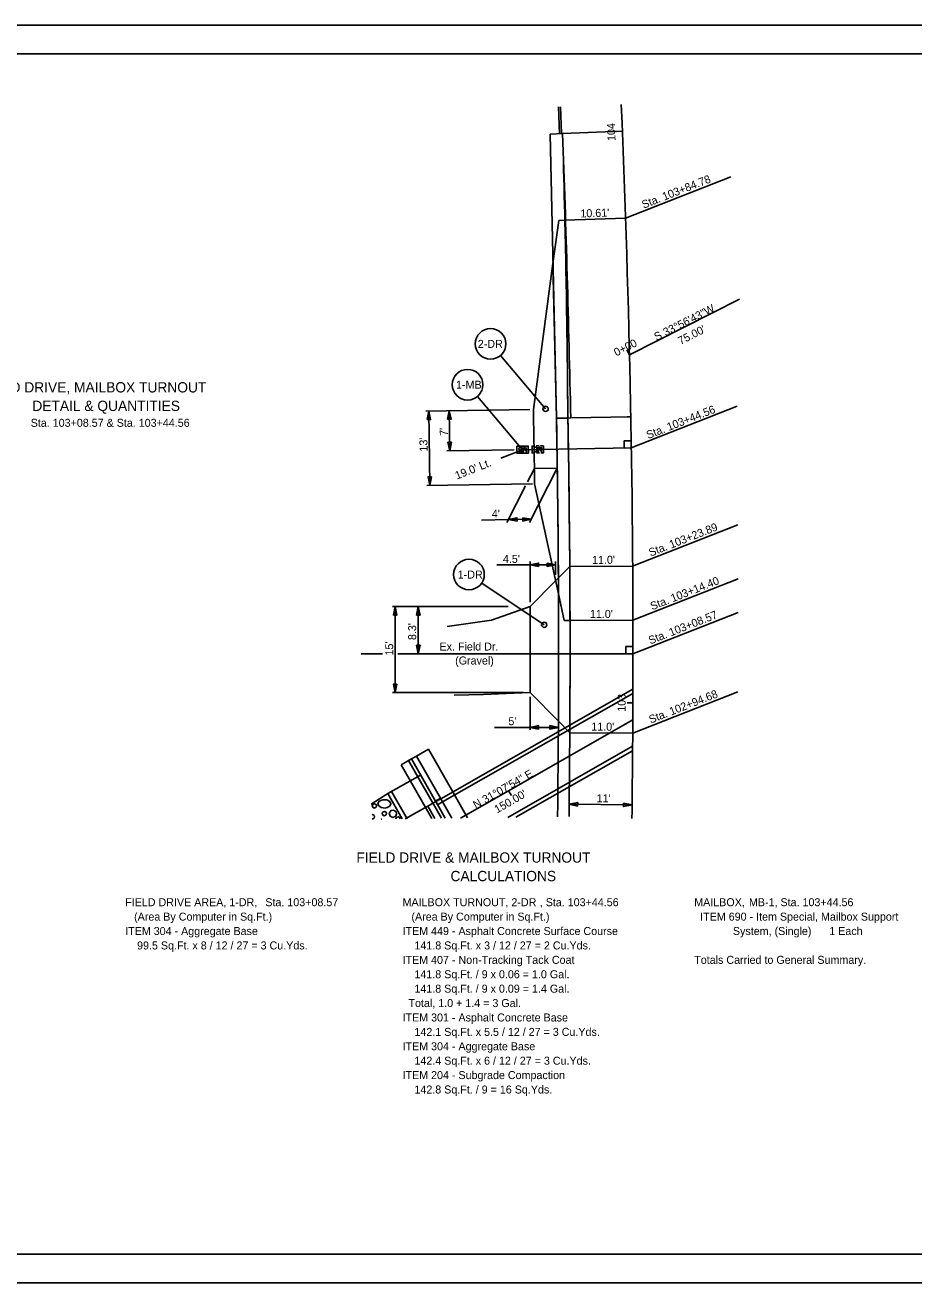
# Model space of a CAD drawing. Extents: x -736 to 9385, y -1086 to 4832.
# Drawn here: x 151.9 to 307.3, y -220 to 0 of the extents above; entities that cross this region are included whole.
import ezdxf

# ---------------------------------------------------------------- set-up
doc = ezdxf.new("R2010")
doc.units = 0
for name, color, linetype in [('_CIVIL_CONSTRUCTION', 7, 'Continuous'), ('DR_P_Culvert', 7, 'Continuous'), ('DR_X_Headwall', 7, 'Continuous'), ('DT_X_Contour_Major', 7, 'Continuous'), ('DT_X_Contour_Text', 7, 'Continuous'), ('DT_X_Island', 7, 'Continuous'), ('DT_X_Terrain_Boundary', 7, 'Continuous'), ('GE_X_Alignment_100_Stations', 7, 'Continuous'), ('GK_Drainage_Nodes', 7, 'Continuous'), ('GT_Project_Soil_Boring', 7, 'Continuous'), ('HY_X_Water_Edge', 7, 'Continuous'), ('PV_P_Drive', 7, 'Continuous'), ('PV_P_Field_Drive', 7, 'Continuous'), ('PV_P_Shoulder', 7, 'Continuous'), ('PV_X_Driveway', 7, 'Continuous'), ('PV_X_Shoulder_Aggregate', 7, 'Continuous'), ('RD_X_Concrete_Pad', 7, 'Continuous'), ('RW_P_Const_Limits', 7, 'Continuous'), ('SC_Scratch1', 7, 'Continuous'), ('SH_Data', 7, 'Continuous'), ('SH_Named_Boundary', 7, 'Continuous'), ('SV_X_Control_Cells_Found', 7, 'Continuous'), ('UT_X_Telecom', 7, 'Continuous'), ('UT_X_Telecom_Cells', 7, 'Continuous'), ('VG_X_Tree_Line_Lt', 7, 'Continuous')]:
    doc.layers.add(name, color=color, linetype=linetype)

msp = doc.modelspace()

# ---------------------------------------------------------------- linework, layer by layer
at = {"layer": '_CIVIL_CONSTRUCTION'}
for p, q in [((256.35, -18.54), (255.35, -18.58)), ((256.35, -18.54), (255.35, -18.58)), ((257.82, -68.52), (257.22, -68.53)), ((257.82, -68.52), (257.22, -68.53)), ((258.19, -118.52), (257.19, -118.52)), ((258.19, -118.52), (257.19, -118.52))]:
    msp.add_line(p, q, dxfattribs=at)
at = {"layer": 'DR_P_Culvert'}
msp.add_lwpolyline([(15, -5), (335, -5), (335, -215), (15, -215)], close=True, dxfattribs=at)
at = {"layer": 'DR_X_Headwall'}
for p, q in [((223.68, -135.73), (223.73, -135.8)), ((224.55, -135.23), (224.59, -135.31))]:
    msp.add_line(p, q, dxfattribs=at)
msp.add_lwpolyline([(224.59, -135.31), (223.73, -135.8), (223.68, -135.73), (224.55, -135.23)], close=True, dxfattribs=at)
at = {"layer": 'DT_X_Contour_Text'}
for p, q in [((256.92, -33.78), (275.3, -26.54)), ((256.92, -33.78), (246.31, -34.14)), ((240.19, -67.24), (221.97, -67.51)), ((222.7, -80.49), (222.51, -67.5)), ((226.19, -74.45), (226.09, -67.45)), ((257.92, -73.96), (276.44, -66.67)), ((237.44, -74.28), (225.68, -74.45)), ((235.12, -75.76), (238.92, -74.26)), ((239.78, -79.9), (240.97, -77.56)), ((240.14, -87.02), (244.97, -77.5)), ((244.97, -77.5), (240.97, -77.56)), ((240.63, -80.23), (222.16, -80.5)), ((236.18, -87), (239.44, -80.57)), ((258.15, -94.63), (276.54, -87.4)), ((234.41, -94.39), (240.21, -94.39)), ((240.21, -100.96), (240.21, -93.83)), ((240.21, -94.39), (244.69, -94.39)), ((244.69, -96.16), (244.69, -93.83)), ((258.15, -94.63), (247.15, -94.71)), ((258.2, -104.1), (276.59, -96.87)), ((236.41, -101.7), (216.15, -101.7)), ((216.65, -116.76), (216.65, -101.7)), ((220.68, -109.95), (220.68, -101.7)), ((258.21, -109.95), (276.59, -102.72)), ((258.2, -104.1), (247.2, -104.13)), ((258.16, -123.83), (276.55, -116.6)), ((239.02, -116.76), (216.15, -116.76)), ((240.21, -123.28), (240.21, -117.49)), ((233.98, -122.83), (240.21, -122.83)), ((240.21, -122.83), (245.17, -122.83)), ((258.16, -123.83), (247.16, -123.77)), ((247.05, -136.28), (258.05, -136.41))]:
    msp.add_line(p, q, dxfattribs=at)
for points in [[(222.24, -69), (222.51, -67.5), (222.83, -68.99)], [(225.81, -68.94), (226.09, -67.45), (226.41, -68.93)], [(226.47, -72.95), (226.19, -74.45), (225.87, -72.96)], [(222.98, -79), (222.7, -80.49), (222.38, -79)], [(237.94, -86.77), (236.44, -86.49), (237.93, -86.17)], [(238.94, -86.16), (240.44, -86.43), (238.95, -86.75)], [(241.7, -94.69), (240.21, -94.39), (241.7, -94.09)], [(243.19, -94.09), (244.69, -94.39), (243.19, -94.69)], [(216.35, -103.19), (216.65, -101.7), (216.95, -103.19)], [(220.38, -103.19), (220.68, -101.7), (220.98, -103.19)], [(220.98, -108.46), (220.68, -109.95), (220.38, -108.46)], [(216.95, -115.27), (216.65, -116.76), (216.35, -115.27)], [(241.7, -123.13), (240.21, -122.83), (241.7, -122.53)], [(243.67, -122.53), (245.17, -122.83), (243.67, -123.13)], [(248.54, -136.6), (247.05, -136.28), (248.55, -136)], [(256.56, -136.1), (258.05, -136.41), (256.55, -136.69)]]:
    msp.add_lwpolyline(points, close=True, dxfattribs=at)
at = {"layer": 'DT_X_Island'}
for p, q in [((244.22, -41.67), (245.23, -34.15)), ((245.23, -34.15), (246.31, -34.14)), ((244.83, -68.76), (244.22, -41.67)), ((242.93, -67.12), (235.04, -57.79)), ((238.92, -74.26), (231.03, -64.93)), ((242.69, -104.89), (231.77, -97.59)), ((247.16, -123.77), (245.17, -121.77))]:
    msp.add_line(p, q, dxfattribs=at)
for centre in [(242.93, -67.12), (242.69, -104.89)]:
    msp.add_circle(centre, 0.461, dxfattribs=at)
for centre, radius, start, end in [((-1969.2, -84.43), 2216.08, 0.406, 1.30035), ((-1993.42, -109.95), 2238.63, 359.69768, 1.05435), ((-1993.42, -109.95), 2240.63, 359.64677, 1.05435)]:
    msp.add_arc(centre, radius, start, end, dxfattribs=at)
at = {"layer": 'DT_X_Terrain_Boundary'}
for centre in [(233.31, -55.75), (229.3, -62.89), (229.54, -96.1)]:
    msp.add_circle(centre, 2.68, dxfattribs=at)
at = {"layer": 'GE_X_Alignment_100_Stations'}
msp.add_line((238.92, -74.26), (238.92, -74.26), dxfattribs=at)
msp.add_lwpolyline([(239.93, -74.85), (237.93, -74.89), (237.91, -73.66), (239.91, -73.63)], close=True, dxfattribs=at)
for points in [[(238.41, -74.3), (238.38, -74.33), (238.36, -74.35), (238.35, -74.37), (238.34, -74.39), (238.33, -74.41), (238.32, -74.43), (238.31, -74.47), (238.31, -74.49), (238.31, -74.52), (238.32, -74.56), (238.33, -74.59), (238.35, -74.61), (238.38, -74.64), (238.41, -74.65), (238.42, -74.65), (238.45, -74.67), (238.76, -74.66), (238.75, -73.86), (238.4, -73.87), (238.36, -73.89), (238.32, -73.93), (238.29, -73.98), (238.27, -74.03), (238.27, -74.09), (238.27, -74.13), (238.28, -74.17), (238.31, -74.22), (238.34, -74.26), (238.41, -74.3), (238.76, -74.3)], [(239.56, -73.85), (239.57, -74.65), (239.27, -73.85), (239.01, -74.66), (238.99, -73.86)]]:
    msp.add_lwpolyline(points, dxfattribs=at)
at = {"layer": 'GK_Drainage_Nodes'}
for p, q in [((244.22, -41.67), (245.23, -34.15)), ((246.31, -34.14), (245.23, -34.15)), ((240.8, -67.23), (244.22, -41.67)), ((241.01, -80.23), (245.18, -99.46)), ((245.18, -99.46), (246.2, -104.15)), ((247.2, -104.13), (246.2, -104.15))]:
    msp.add_line(p, q, dxfattribs=at)
msp.add_arc((-1993.42, -109.95), 2234.63, 0.76225, 1.09547, dxfattribs=at)
at = {"layer": 'GT_Project_Soil_Boring'}
msp.add_line((245.17, -14.28), (245.38, -18.99), dxfattribs=at)
at = {"layer": 'HY_X_Water_Edge'}
for p, q in [((220.34, -127.85), (222.44, -126.65)), ((226.69, -134.11), (222.44, -126.65)), ((217.66, -129.38), (219.47, -128.35)), ((223.02, -138.77), (217.66, -129.38)), ((224.73, -138.74), (218.97, -128.63)), ((220.34, -127.85), (219.47, -128.35)), ((223.68, -135.73), (219.47, -128.35)), ((224.55, -135.23), (220.34, -127.85)), ((218.74, -138.83), (216.02, -134.06)), ((229.3, -138.68), (226.69, -134.11)), ((223.73, -135.8), (222.35, -136.59)), ((224.55, -135.23), (223.68, -135.73)), ((223.73, -135.8), (225.4, -138.73)), ((224.59, -135.31), (226.54, -138.72)), ((223.59, -138.76), (222.35, -136.59))]:
    msp.add_line(p, q, dxfattribs=at)
at = {"layer": 'PV_P_Drive'}
for p, q in [((256.35, -18.54), (245.91, -18.97)), ((246.83, -68.72), (247.34, -68.71)), ((247.34, -68.71), (257.82, -68.52)), ((257.92, -73.96), (238.92, -74.26)), ((236.44, -86.49), (231.74, -86.57)), ((240.44, -86.43), (236.44, -86.49)), ((214.39, -109.95), (210.71, -109.95)), ((258.21, -109.95), (217.11, -109.95))]:
    msp.add_line(p, q, dxfattribs=at)
for points in [[(257.92, -73.96), (256.67, -73.98), (256.65, -72.73), (257.9, -72.71)], [(258.21, -109.95), (256.96, -109.95), (256.96, -108.7), (258.21, -108.7)]]:
    msp.add_lwpolyline(points, close=True, dxfattribs=at)
for centre, radius, start, end in [((-3028.28, -137.41), 3276.33, 1.20138, 2.07168), ((-1969.2, -84.43), 2216.08, 0.406, 1.69265), ((-1993.42, -109.95), 2240.63, 359.27159, 1.05435)]:
    msp.add_arc(centre, radius, start, end, dxfattribs=at)
at = {"layer": 'PV_P_Field_Drive'}
for p, q in [((257.6, -57.67), (276.84, -47.91)), ((236.46, -133.91), (258.18, -121.52)), ((236.46, -133.91), (228.06, -138.7))]:
    msp.add_line(p, q, dxfattribs=at)
for start, end in [(359.78203, 2.44543), (359.26709, 359.78203)]:
    msp.add_arc((-1993.42, -109.95), 2251.63, start, end, dxfattribs=at)
at = {"layer": 'PV_P_Shoulder'}
for p, q in [((340, 0), (0, 0)), ((0, 0), (340, 0)), ((0, -220), (340, -220))]:
    msp.add_line(p, q, dxfattribs=at)
at = {"layer": 'PV_X_Driveway'}
for p, q in [((215.36, -134.43), (212.46, -136.26)), ((212.95, -138.72), (212.64, -138.87))]:
    msp.add_line(p, q, dxfattribs=at)
for points in [[(213.31, -136.81), (212.99, -136.96), (212.7, -136.82), (212.62, -136.51), (212.81, -136.24), (213.06, -136.19), (213.33, -136.37), (213.39, -136.57), (213.31, -136.81)], [(214.87, -136.94), (214.2, -136.85), (213.71, -136.52), (213.6, -136.16), (213.84, -135.76), (214.46, -135.5), (215.18, -135.53), (215.72, -135.81), (215.9, -136.19), (215.69, -136.63), (215.24, -136.87), (214.84, -136.94)], [(212.59, -138.12), (212.71, -138.1), (212.97, -138.27), (213.03, -138.47), (212.95, -138.72)], [(215.05, -138.14), (214.73, -138.3), (214.44, -138.16), (214.36, -137.84), (214.55, -137.58), (214.8, -137.53), (215.07, -137.7), (215.13, -137.9), (215.05, -138.14)], [(216.76, -138.35), (216.24, -138.6), (215.75, -138.36), (215.61, -137.84), (215.93, -137.4), (216.35, -137.32), (216.79, -137.61), (216.89, -137.94), (216.76, -138.34)], [(216.76, -138.85), (216.75, -138.79), (216.93, -138.53), (217.19, -138.48), (217.45, -138.65), (217.51, -138.84)], [(214.18, -138.89), (214.27, -138.87), (214.29, -138.89)]]:
    msp.add_lwpolyline(points, dxfattribs=at)
at = {"layer": 'PV_X_Shoulder_Aggregate'}
msp.add_line((245.54, -14.27), (245.71, -18.98), dxfattribs=at)
at = {"layer": 'RD_X_Concrete_Pad'}
for p, q in [((258.2, -116.13), (224.59, -135.31)), ((258.19, -116.9), (224.92, -135.88)), ((258.15, -126.14), (236.33, -138.58)), ((258.14, -126.91), (237.71, -138.57)), ((224.59, -135.31), (223.73, -135.8)), ((224.92, -135.88), (224.06, -136.38))]:
    msp.add_line(p, q, dxfattribs=at)
at = {"layer": 'RW_P_Const_Limits'}
for p, q in [((219.47, -128.35), (223.68, -135.73)), ((215.36, -134.43), (217.88, -138.84))]:
    msp.add_line(p, q, dxfattribs=at)
at = {"layer": 'SC_Scratch1'}
for p, q in [((245.91, -18.97), (243.72, -19.06)), ((244.83, -68.76), (243.72, -19.06)), ((244.83, -68.76), (246.83, -68.72))]:
    msp.add_line(p, q, dxfattribs=at)
msp.add_arc((-1993.42, -109.95), 2238.63, 359.27024, 1.05435, dxfattribs=at)
at = {"layer": 'SH_Data'}
for p, q in [((257.6, -57.67), (257.15, -56.78)), ((257.6, -57.67), (257.15, -56.78)), ((236.46, -133.91), (236.96, -134.78))]:
    msp.add_line(p, q, dxfattribs=at)
at = {"layer": 'SV_X_Control_Cells_Found'}
for p, q in [((221.08, -131.17), (215.36, -134.43)), ((217.88, -138.84), (215.36, -134.43)), ((222.35, -136.59), (218.41, -138.83))]:
    msp.add_line(p, q, dxfattribs=at)
at = {"layer": 'UT_X_Telecom'}
for points in [[(240.21, -101.7), (233.47, -104.08), (225.72, -105.21)], [(240.21, -116.76), (237.39, -116.87), (232.1, -117.1), (226.93, -117.18)]]:
    msp.add_lwpolyline(points, dxfattribs=at)
at = {"layer": 'UT_X_Telecom_Cells'}
for p, q in [((241.81, -73.6), (241.31, -73.61)), ((241.57, -74.22), (241.57, -74.22)), ((241.84, -74.82), (241.34, -74.83))]:
    msp.add_line(p, q, dxfattribs=at)
for points in [[(240.57, -74.11), (240.56, -73.62), (241.05, -73.62)], [(241.08, -74.84), (240.58, -74.85), (240.57, -74.36)], [(241.06, -74.26), (241.03, -74.29), (241.01, -74.31), (241, -74.33), (240.99, -74.34), (240.98, -74.37), (240.97, -74.39), (240.96, -74.43), (240.96, -74.45), (240.96, -74.48), (240.97, -74.51), (240.98, -74.55), (241, -74.57), (241.03, -74.6), (241.06, -74.61), (241.07, -74.61), (241.1, -74.63), (241.41, -74.62), (241.4, -73.82), (241.05, -73.83), (241.01, -73.85), (240.97, -73.88), (240.94, -73.94), (240.92, -73.99), (240.92, -74.05), (240.92, -74.09), (240.93, -74.12), (240.96, -74.18), (240.99, -74.22), (241.06, -74.26), (241.41, -74.25)], [(242.21, -73.81), (242.22, -74.61), (241.92, -73.81), (241.66, -74.62), (241.64, -73.82)], [(242.07, -73.6), (242.56, -73.59), (242.57, -74.07)], [(242.57, -74.32), (242.58, -74.81), (242.1, -74.82)]]:
    msp.add_lwpolyline(points, dxfattribs=at)
at = {"layer": 'VG_X_Tree_Line_Lt'}
for p, q in [((247.15, -94.71), (244.69, -97.19)), ((244.69, -97.19), (240.21, -101.7)), ((240.21, -109.95), (240.21, -101.7)), ((240.21, -109.95), (240.21, -116.76)), ((245.17, -121.77), (240.21, -116.76)), ((245.17, -121.77), (247.16, -123.77))]:
    msp.add_line(p, q, dxfattribs=at)

# ---------------------------------------------------------------- texts
at = {"layer": '_CIVIL_CONSTRUCTION'}
for s, rotation, p in [('104', 92.3267, (255.17, -20.23)), ('103', 89.782, (256.93, -120.11))]:
    msp.add_text(s, height=1.4, rotation=rotation, dxfattribs=at).set_placement(p)
at = {"layer": 'DT_X_Contour_Major'}
for s, p in [('FIELD DRIVE, MAILBOX TURNOUT', (144.3, -64.25)), ('DETAIL & QUANTITIES', (153.2, -67.49)), ('FIELD DRIVE & MAILBOX TURNOUT', (209.85, -146.5)), ('CALCULATIONS', (226.31, -149.74))]:
    msp.add_text(s, height=1.8, dxfattribs=at).set_placement(p)
at = {"layer": 'DT_X_Contour_Text'}
for s, rotation, p in [('Sta. 103+84.78', 21.4812, (260.08, -32.12)), ('Sta. 103+44.56', 21.4812, (260.88, -72.41)), ("13'", 90.8387, (222.3, -74.58)), ("7'", 90.8387, (225.85, -71.83)), ("19.0' Lt.", 21.4812, (227.43, -79.5)), ('Sta. 103+23.89', 21.4812, (261.3, -92.98)), ("4.5'", 360, (235.47, -94.07)), ('Sta. 103+14.40', 21.4812, (261.56, -102.37)), ('Sta. 103+08.57', 21.4812, (261.25, -108.34)), ("8.3'", 90, (220.3, -107.56)), ("15'", 90, (216.29, -110.26)), ('Sta. 102+94.68', 21.4812, (261.32, -122.18)), ("5'", 360, (236.43, -122.46)), ("11'", 359.3267, (251.86, -135.93))]:
    msp.add_text(s, height=1.4, rotation=rotation, dxfattribs=at).set_placement(p)
for s, p in [('Sta. 103+08.57 & Sta. 103+44.56', (152.91, -70.26)), ('Ex. Field Dr.', (224.39, -109.39)), ('(Gravel)', (227.12, -111.84))]:
    msp.add_text(s, height=1.4, dxfattribs=at).set_placement(p)
at = {"layer": 'DT_X_Terrain_Boundary'}
for s, rotation, p in [("10.61'", 1.9388, (249.04, -33.65)), ("4'", 360, (233.53, -86.17)), ("11.0'", 0.3899, (251.06, -94.24)), ("11.0'", 359.6468, (250.93, -123.39))]:
    msp.add_text(s, height=1.4, rotation=rotation, dxfattribs=at).set_placement(p)
for s, p in [('2-DR', (231.08, -56.45)), ('1-MB', (227.28, -63.59)), ('1-DR', (227.57, -96.8)), ("11.0'", (250.68, -103.69)), ('FIELD DRIVE AREA, 1-DR,', (169.43, -154.12)), (' Sta. 103+08.57', (193.41, -154.12)), ('MAILBOX TURNOUT, 2-DR', (217.92, -154.12)), (', Sta. 103+44.56', (241.91, -154.12)), ('MAILBOX,', (268.92, -154.12)), (' MB-1, Sta. 103+44.56', (277.97, -154.12)), ('   (Area By Computer in Sq.Ft.)', (169.43, -156.64)), ('   (Area By Computer in Sq.Ft.)', (217.92, -156.64)), ('  ITEM 690 - Item Special, Mailbox Support', (268.92, -156.64)), ('ITEM 304 - Aggregate Base', (169.43, -159.16)), ('ITEM 449 - Asphalt Concrete Surface Course', (217.92, -159.16)), ('             System, (Single)      1 Each ', (268.92, -159.16)), ('    99.5 Sq.Ft. x 8 / 12 / 27 = 3 Cu.Yds.', (169.43, -161.68)), ('    141.8 Sq.Ft. x 3 / 12 / 27 = 2 Cu.Yds.', (217.92, -161.68)), ('ITEM 407 - Non-Tracking Tack Coat', (217.92, -164.2)), ('Totals Carried to General Summary.', (268.92, -164.2)), ('    141.8 Sq.Ft. / 9 x 0.06 = 1.0 Gal.', (217.92, -166.72)), ('    141.8 Sq.Ft. / 9 x 0.09 = 1.4 Gal.', (217.92, -169.24)), ('  Total, 1.0 + 1.4 = 3 Gal.', (217.92, -171.76)), ('ITEM 301 - Asphalt Concrete Base', (217.92, -174.28)), ('    142.1 Sq.Ft. x 5.5 / 12 / 27 = 3 Cu.Yds.', (217.92, -176.8)), ('ITEM 304 - Aggregate Base', (217.92, -179.32)), ('    142.4 Sq.Ft. x 6 / 12 / 27 = 3 Cu.Yds.', (217.92, -181.84)), ('ITEM 204 - Subgrade Compaction', (217.92, -184.36)), ('    142.8 Sq.Ft. / 9 = 16 Sq.Yds.', (217.92, -186.88))]:
    msp.add_text(s, height=1.4, dxfattribs=at).set_placement(p)
at = {"layer": 'SH_Data'}
for s, rotation, p in [('0+00', 26.8922, (255.31, -57.97)), ('N 31°07\'54" E', 29.7057, (230.74, -137.12)), ("150.00'", 29.7057, (234.46, -137.9))]:
    msp.add_text(s, height=1.4, rotation=rotation, dxfattribs=at).set_placement(p)
at = {"layer": 'SH_Named_Boundary'}
for s, p in [('S 33°56\'43"W', (262.34, -55.24)), ("75.00'", (266.53, -55.95))]:
    msp.add_text(s, height=1.4, rotation=26.8922, dxfattribs=at).set_placement(p)

doc.saveas('drawing.dxf')
